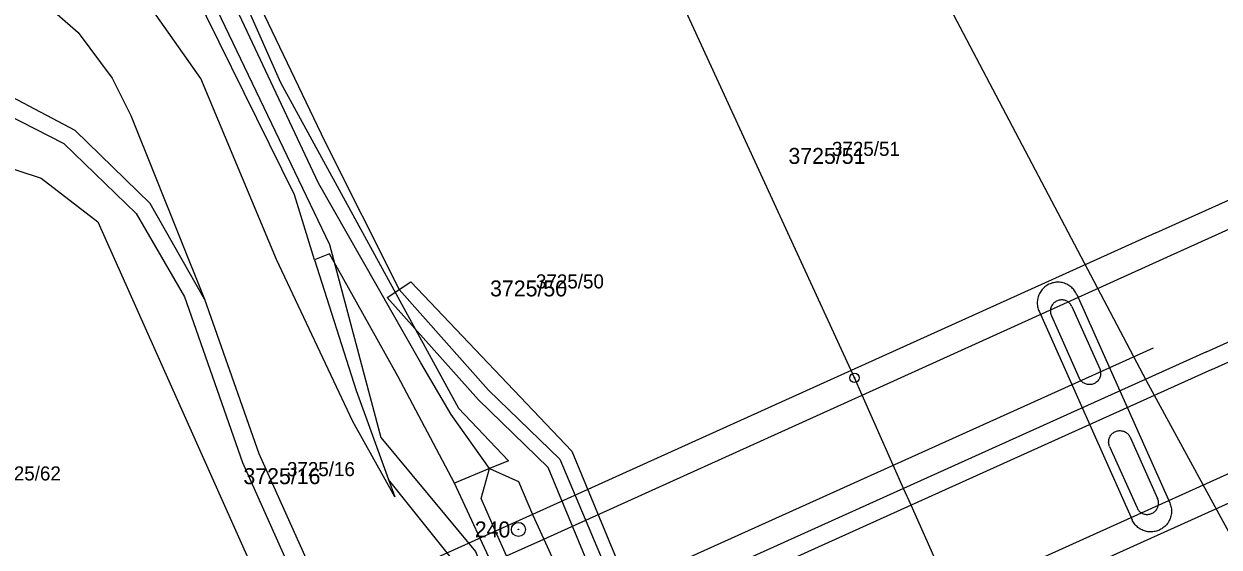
# Model space of a CAD drawing. Extents: x -755751 to -744370, y -967072 to -958435.
# Drawn here: x -747476.3 to -747348.7, y -965410.5 to -965354.8 of the extents above; entities that cross this region are included whole.
import ezdxf

# ---------------------------------------------------------------- set-up
doc = ezdxf.new("R2010")
doc.units = 0
for name, color, linetype in [('Vrstva 1', 7, 'Continuous'), ('Vrstva 13', 7, 'Continuous'), ('Vrstva 2', 7, 'Continuous'), ('Vrstva 3', 7, 'Continuous'), ('Vrstva 35', 7, 'Continuous'), ('Vrstva 4', 7, 'Continuous'), ('Vrstva 42', 7, 'Continuous'), ('Vrstva 50', 7, 'Continuous'), ('Vrstva 8', 7, 'Continuous')]:
    doc.layers.add(name, color=color, linetype=linetype)

# ---------------------------------------------------------------- blocks, each defined once
blk = doc.blocks.new('1.01')
at = {"layer": 'Vrstva 8'}
for radius in [0.75, 0.03]:
    blk.add_circle((0, 0.001), radius, dxfattribs=at)
blk = doc.blocks.new('1.05')
at = {"layer": 'Vrstva 8'}
for radius in [0.5, 0.0303]:
    blk.add_circle((0, 0), radius, dxfattribs=at)

msp = doc.modelspace()

# ---------------------------------------------------------------- linework, layer by layer
at = {"layer": 'Vrstva 1'}
for points in [[(-747445.23, -965379.92), (-747447.37, -965372.98), (-747460.79, -965345.82), (-747472.15, -965319.18), (-747476.112, -965311.216)], [(-747471.26, -965311.216), (-747467.96, -965317.93), (-747448.87, -965361), (-747429.89, -965395.74), (-747424.56, -965401.33), (-747426.57, -965402.17)], [(-747279.165, -965572.766), (-747279.19, -965572.72), (-747318.1, -965501.72), (-747320.58, -965502.66), (-747342.67, -965465.16), (-747352.78, -965470.55), (-747357.13, -965461.03), (-747376, -965418.63), (-747377.18, -965415.98), (-747381.59, -965406.09), (-747382.39, -965404.29), (-747386.82, -965394.33), (-747387.63, -965392.51), (-747387.99, -965391.72), (-747425.054, -965311.216)], [(-747313.39, -965471.85), (-747356.48, -965392.83), (-747396.55, -965316.79), (-747397.43, -965314.99)], [(-747437.34, -965403.35), (-747436.67, -965405.18), (-747441.17, -965397.15), (-747449.31, -965379.9), (-747457.39, -965360.59), (-747463.67, -965351.63), (-747474.03, -965344.07), (-747484.32, -965340.2), (-747495.09, -965339.27), (-747504.04, -965340.87), (-747516.35, -965346.17), (-747522.34, -965351.17)], [(-747534.71, -965373.37), (-747531.66, -965370.7), (-747512.73, -965353.63), (-747508.57, -965350.62), (-747502.21, -965347.61), (-747497.27, -965346.29), (-747492.14, -965345.95), (-747486.69, -965346.48), (-747480.57, -965348.43), (-747475.22, -965351.48), (-747470.46, -965355.7), (-747466.83, -965360.55), (-747464.83, -965364.53), (-747457, -965384.11)], [(-747457, -965384.11), (-747462.79, -965373.92), (-747470.78, -965366.13), (-747483.64, -965359.33), (-747498.12, -965356.84), (-747517.2, -965361.3), (-747534.71, -965373.37)], [(-747580, -965419.59), (-747576.93, -965416.19), (-747570.41, -965408.98), (-747568.93, -965407.34), (-747555.66, -965395.12), (-747533.62, -965375.09), (-747516.44, -965363.14), (-747498.44, -965358.86), (-747484.39, -965361.2), (-747471.99, -965367.52), (-747464.29, -965374.98), (-747459.13, -965383.85), (-747452.93, -965401.54), (-747433.5, -965444.94), (-747432.43, -965449.21), (-747433.12, -965451.71), (-747436.62, -965454.67)], [(-747491.54, -965365.61), (-747474.4, -965371.21), (-747468.36, -965375.87), (-747448.92, -965419.41)], [(-747426.57, -965402.17), (-747430.32, -965403.74), (-747436.36, -965392.33), (-747443.64, -965379.27), (-747445.23, -965379.92)], [(-747445.23, -965379.92), (-747440.81, -965393.86), (-747437.34, -965403.35)], [(-747457, -965384.11), (-747451.17, -965400.56), (-747431.47, -965444.37), (-747430.45, -965449.46)], [(-747425.95, -965408.84), (-747427.45, -965405.35), (-747426.57, -965402.17)], [(-747421.02, -965440.66), (-747424.84, -965423.83), (-747429.68, -965412.94), (-747437.34, -965403.35)], [(-747413.8, -965435.67), (-747414.99, -965433.04), (-747419.46, -965423.17), (-747420.28, -965421.37), (-747424.76, -965411.47), (-747425.95, -965408.84)]]:
    msp.add_lwpolyline(points, dxfattribs=at)
at = {"layer": 'Vrstva 13'}
msp.add_lwpolyline([(-747331.13, -965546.93), (-747315.45, -965583.53), (-747318.21, -965584.71), (-747332.83, -965550.59), (-747357.69, -965558.3), (-747380.08, -965501.06), (-747404.05, -965441.38), (-747413.52, -965445.4), (-747414.7, -965442.64), (-747405.18, -965438.6), (-747420.33, -965402.04), (-747427.76, -965394.84), (-747437.48, -965383.95), (-747434.96, -965382.27), (-747417.79, -965400.32), (-747401.84, -965438.83), (-747377.3, -965499.96), (-747355.91, -965554.6)], close=True, dxfattribs=at)
at = {"layer": 'Vrstva 3'}
msp.add_lwpolyline([(-747475.524, -965310.657), (-747463.076, -965337.78), (-747443.661, -965378.272), (-747438.156, -965398.843), (-747428.072, -965411.013), (-747420.077, -965431.054), (-747417.066, -965444.853), (-747389.85, -965506.361), (-747363.472, -965564.291), (-747356.615, -965583.303), (-747355.471, -965592.352), (-747358.691, -965612.368), (-747371.15, -965609.362), (-747381.735, -965618.581), (-747393.483, -965621.91), (-747403.048, -965622.014), (-747420.59, -965617.228)], dxfattribs=at)
at = {"layer": 'Vrstva 35'}
msp.add_lwpolyline([(-747472.549, -965305.898), (-747472.22, -965306.61), (-747462.76, -965327.52), (-747453.81, -965347.07), (-747444.13, -965367.31), (-747436.22, -965383.1), (-747426.68, -965393.8), (-747419.06, -965401.18), (-747405.68, -965432.89), (-747403.23, -965439.404)], dxfattribs=at)
at = {"layer": 'Vrstva 4'}
for points in [[(-747444.82, -965371.76), (-747473.291, -965311.216)], [(-747355.47, -965377.05), (-747316.19, -965359.38)], [(-747354.3, -965379.65), (-747314.8, -965361.81)], [(-747433.91, -965390.91), (-747444.82, -965371.76)], [(-747350.06, -965389.71), (-747310.05, -965371.67)], [(-747349.5, -965391.61), (-747309, -965373.41)], [(-747355.47, -965377.05), (-747387.99, -965391.72)], [(-747386.82, -965394.33), (-747354.3, -965379.65)], [(-747363.92, -965383.61), (-747363.977, -965383.493), (-747364.041, -965383.379), (-747364.111, -965383.269), (-747364.188, -965383.163), (-747364.27, -965383.062), (-747364.359, -965382.966), (-747364.453, -965382.876), (-747364.553, -965382.791), (-747364.657, -965382.713), (-747364.766, -965382.641), (-747364.878, -965382.575), (-747364.995, -965382.516), (-747365.115, -965382.464), (-747365.237, -965382.419), (-747365.362, -965382.382), (-747365.489, -965382.352), (-747365.618, -965382.33), (-747365.748, -965382.315), (-747365.878, -965382.308), (-747366.009, -965382.309), (-747366.139, -965382.318), (-747366.268, -965382.334), (-747366.397, -965382.358), (-747366.523, -965382.389), (-747366.648, -965382.428), (-747366.77, -965382.474), (-747366.889, -965382.528), (-747367.005, -965382.588), (-747367.117, -965382.655), (-747367.225, -965382.728), (-747367.328, -965382.808), (-747367.426, -965382.894), (-747367.519, -965382.986), (-747367.607, -965383.082), (-747367.689, -965383.184), (-747367.764, -965383.291), (-747367.833, -965383.402), (-747367.895, -965383.516), (-747367.951, -965383.634), (-747367.999, -965383.756), (-747368.04, -965383.88), (-747368.074, -965384.006), (-747368.1, -965384.134), (-747368.118, -965384.263), (-747368.129, -965384.393), (-747368.132, -965384.523), (-747368.128, -965384.654), (-747368.115, -965384.784), (-747368.095, -965384.913), (-747368.068, -965385.04), (-747368.032, -965385.166), (-747367.99, -965385.289), (-747367.94, -965385.41)], [(-747363.92, -965383.61), (-747354, -965405.83)], [(-747364.44, -965384.9), (-747364.483, -965384.813), (-747364.534, -965384.731), (-747364.59, -965384.652), (-747364.653, -965384.579), (-747364.722, -965384.51), (-747364.795, -965384.448), (-747364.874, -965384.391), (-747364.957, -965384.341), (-747365.044, -965384.298), (-747365.133, -965384.262), (-747365.226, -965384.234), (-747365.32, -965384.213), (-747365.416, -965384.199), (-747365.513, -965384.194), (-747365.61, -965384.196), (-747365.706, -965384.206), (-747365.801, -965384.223), (-747365.894, -965384.248), (-747365.986, -965384.281), (-747366.074, -965384.321), (-747366.158, -965384.368), (-747366.239, -965384.421), (-747366.315, -965384.481), (-747366.386, -965384.547), (-747366.452, -965384.618), (-747366.511, -965384.694), (-747366.564, -965384.775), (-747366.611, -965384.86), (-747366.651, -965384.948), (-747366.683, -965385.039), (-747366.708, -965385.133), (-747366.725, -965385.228), (-747366.735, -965385.324), (-747366.736, -965385.421), (-747366.73, -965385.518), (-747366.717, -965385.614), (-747366.695, -965385.708), (-747366.666, -965385.8), (-747366.63, -965385.89)], [(-747364.44, -965384.9), (-747361.47, -965391.54)], [(-747367.94, -965385.41), (-747358.02, -965407.62)], [(-747366.63, -965385.89), (-747363.66, -965392.52)], [(-747350.06, -965389.71), (-747382.39, -965404.29)], [(-747430.68, -965396.39), (-747433.91, -965390.91)], [(-747349.5, -965391.61), (-747381.59, -965406.09)], [(-747361.47, -965391.54), (-747361.435, -965391.63), (-747361.407, -965391.722), (-747361.386, -965391.816), (-747361.373, -965391.911), (-747361.368, -965392.007), (-747361.371, -965392.104), (-747361.381, -965392.199), (-747361.399, -965392.294), (-747361.424, -965392.387), (-747361.457, -965392.477), (-747361.497, -965392.565), (-747361.544, -965392.649), (-747361.597, -965392.729), (-747361.657, -965392.805), (-747361.722, -965392.875), (-747361.793, -965392.94), (-747361.869, -965392.999), (-747361.95, -965393.052), (-747362.034, -965393.098), (-747362.122, -965393.138), (-747362.213, -965393.17), (-747362.306, -965393.195), (-747362.401, -965393.212), (-747362.496, -965393.221), (-747362.593, -965393.223), (-747362.689, -965393.217), (-747362.784, -965393.204), (-747362.878, -965393.183), (-747362.97, -965393.154), (-747363.059, -965393.118), (-747363.145, -965393.075), (-747363.228, -965393.026), (-747363.306, -965392.97), (-747363.379, -965392.907), (-747363.448, -965392.839), (-747363.51, -965392.766), (-747363.567, -965392.688), (-747363.617, -965392.606), (-747363.66, -965392.52)], [(-747387.99, -965391.72), (-747421.99, -965407.05)], [(-747420.79, -965409.68), (-747386.82, -965394.33)], [(-747426.57, -965402.17), (-747430.68, -965396.39)], [(-747360.41, -965399.82), (-747360.446, -965399.73), (-747360.475, -965399.638), (-747360.496, -965399.544), (-747360.51, -965399.448), (-747360.515, -965399.351), (-747360.513, -965399.254), (-747360.504, -965399.158), (-747360.486, -965399.063), (-747360.461, -965398.97), (-747360.428, -965398.879), (-747360.389, -965398.79), (-747360.342, -965398.706), (-747360.288, -965398.625), (-747360.229, -965398.549), (-747360.163, -965398.478), (-747360.092, -965398.413), (-747360.015, -965398.353), (-747359.935, -965398.3), (-747359.85, -965398.253), (-747359.761, -965398.214), (-747359.67, -965398.182), (-747359.577, -965398.157), (-747359.482, -965398.14), (-747359.385, -965398.13), (-747359.289, -965398.128), (-747359.192, -965398.134), (-747359.096, -965398.148), (-747359.002, -965398.17), (-747358.91, -965398.199), (-747358.82, -965398.235), (-747358.734, -965398.279), (-747358.651, -965398.329), (-747358.573, -965398.386), (-747358.499, -965398.449), (-747358.431, -965398.518), (-747358.369, -965398.592), (-747358.313, -965398.67), (-747358.263, -965398.753), (-747358.22, -965398.84)], [(-747358.22, -965398.84), (-747355.3, -965405.37)], [(-747360.41, -965399.82), (-747357.49, -965406.35)], [(-747377.18, -965415.98), (-747345.66, -965401.77)], [(-747426.57, -965402.17), (-747423.49, -965403.54)], [(-747425.73, -965413.62), (-747430.32, -965403.74)], [(-747423.49, -965403.54), (-747421.99, -965407.05)], [(-747382.39, -965404.29), (-747416.28, -965419.57)], [(-747344.47, -965404.41), (-747376, -965418.63)], [(-747357.49, -965406.35), (-747357.447, -965406.436), (-747357.397, -965406.519), (-747357.341, -965406.597), (-747357.278, -965406.671), (-747357.21, -965406.739), (-747357.137, -965406.802), (-747357.058, -965406.858), (-747356.976, -965406.908), (-747356.889, -965406.951), (-747356.8, -965406.987), (-747356.708, -965407.016), (-747356.614, -965407.037), (-747356.518, -965407.051), (-747356.422, -965407.057), (-747356.326, -965407.055), (-747356.23, -965407.046), (-747356.135, -965407.029), (-747356.041, -965407.004), (-747355.95, -965406.972), (-747355.862, -965406.932), (-747355.778, -965406.886), (-747355.697, -965406.833), (-747355.621, -965406.773), (-747355.55, -965406.708), (-747355.484, -965406.637), (-747355.425, -965406.562), (-747355.371, -965406.481), (-747355.324, -965406.397), (-747355.285, -965406.309), (-747355.252, -965406.218), (-747355.227, -965406.125), (-747355.209, -965406.03), (-747355.199, -965405.934), (-747355.197, -965405.838), (-747355.202, -965405.742), (-747355.215, -965405.646), (-747355.236, -965405.552), (-747355.264, -965405.46), (-747355.3, -965405.37)], [(-747381.59, -965406.09), (-747415.46, -965421.36)], [(-747354, -965405.83), (-747353.951, -965405.951), (-747353.909, -965406.074), (-747353.874, -965406.2), (-747353.847, -965406.327), (-747353.827, -965406.456), (-747353.815, -965406.586), (-747353.811, -965406.716), (-747353.814, -965406.846), (-747353.825, -965406.976), (-747353.844, -965407.105), (-747353.871, -965407.232), (-747353.905, -965407.358), (-747353.946, -965407.482), (-747353.994, -965407.603), (-747354.05, -965407.721), (-747354.113, -965407.835), (-747354.182, -965407.945), (-747354.257, -965408.051), (-747354.339, -965408.153), (-747354.427, -965408.249), (-747354.52, -965408.341), (-747354.618, -965408.426), (-747354.721, -965408.505), (-747354.829, -965408.579), (-747354.941, -965408.645), (-747355.057, -965408.705), (-747355.176, -965408.758), (-747355.298, -965408.804), (-747355.422, -965408.843), (-747355.549, -965408.874), (-747355.677, -965408.897), (-747355.806, -965408.913), (-747355.936, -965408.922), (-747356.067, -965408.922), (-747356.197, -965408.915), (-747356.326, -965408.9), (-747356.455, -965408.878), (-747356.581, -965408.848), (-747356.706, -965408.81), (-747356.829, -965408.765), (-747356.948, -965408.713), (-747357.064, -965408.654), (-747357.177, -965408.589), (-747357.285, -965408.516), (-747357.389, -965408.438), (-747357.488, -965408.353), (-747357.582, -965408.263), (-747357.671, -965408.167), (-747357.753, -965408.066), (-747357.83, -965407.961), (-747357.9, -965407.851), (-747357.963, -965407.737), (-747358.02, -965407.62)], [(-747421.99, -965407.05), (-747425.95, -965408.84)], [(-747421.99, -965407.05), (-747420.79, -965409.68)], [(-747425.95, -965408.84), (-747511.58, -965447.46)], [(-747424.76, -965411.47), (-747420.79, -965409.68)], [(-747420.79, -965409.68), (-747416.28, -965419.57)]]:
    msp.add_lwpolyline(points, dxfattribs=at)
at = {"layer": 'Vrstva 42'}
msp.add_line((-747355.776, -965389.319), (-747516.15, -965461.6), dxfattribs=at)

# ---------------------------------------------------------------- block references
at = {"layer": 'Vrstva 8'}
for name, p in [('1.05', (-747387.63, -965392.51)), ('1.01', (-747423.49, -965408.66))]:
    msp.add_blockref(name, p, dxfattribs=at)

# ---------------------------------------------------------------- texts
at = {"layer": 'Vrstva 2'}
for s, p in [('3725/51', (-747390.04, -965368.84)), ('3725/50', (-747421.62, -965382.97)), ('3725/62', (-747479.56, -965403.44)), ('3725/16', (-747448.19, -965402.98))]:
    msp.add_text(s, height=1.5, dxfattribs=at).set_placement(p)
at = {"layer": 'Vrstva 50'}
for s, p in [('3725/51', (-747394.681, -965369.69)), ('3725/50', (-747426.515, -965383.82)), ('3725/16', (-747452.831, -965403.83))]:
    msp.add_text(s, height=1.7, dxfattribs=at).set_placement(p)
at = {"layer": 'Vrstva 8'}
msp.add_text('240', height=1.7, dxfattribs=at).set_placement((-747428.148, -965409.51))

doc.saveas('drawing.dxf')
